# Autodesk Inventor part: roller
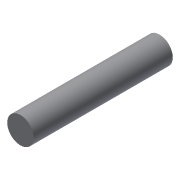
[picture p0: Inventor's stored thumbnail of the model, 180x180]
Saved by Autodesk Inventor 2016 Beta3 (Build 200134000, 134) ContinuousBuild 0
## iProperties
Created: 2016-03
Part Number: roller
Material: Generic
Document SubType Name: Modeling
Designer: Gaurav
Density: 1 g/cm^3
Appearance: Default
Author: Gaurav
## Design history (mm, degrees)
sketch "Sketch1"
  geometry: C1 r 6.937 at (-54.893, 27.064); 1 further point
  constraints: 1 centre point
  dimensions: "d0" = 73.025 dimension on point (0, 0) C1.centre C1
extrude "Extrusion1" new body sketch "Sketch1" distance "d0" = 73.025; taper "d1" = 0 deg
body "Solid1"
